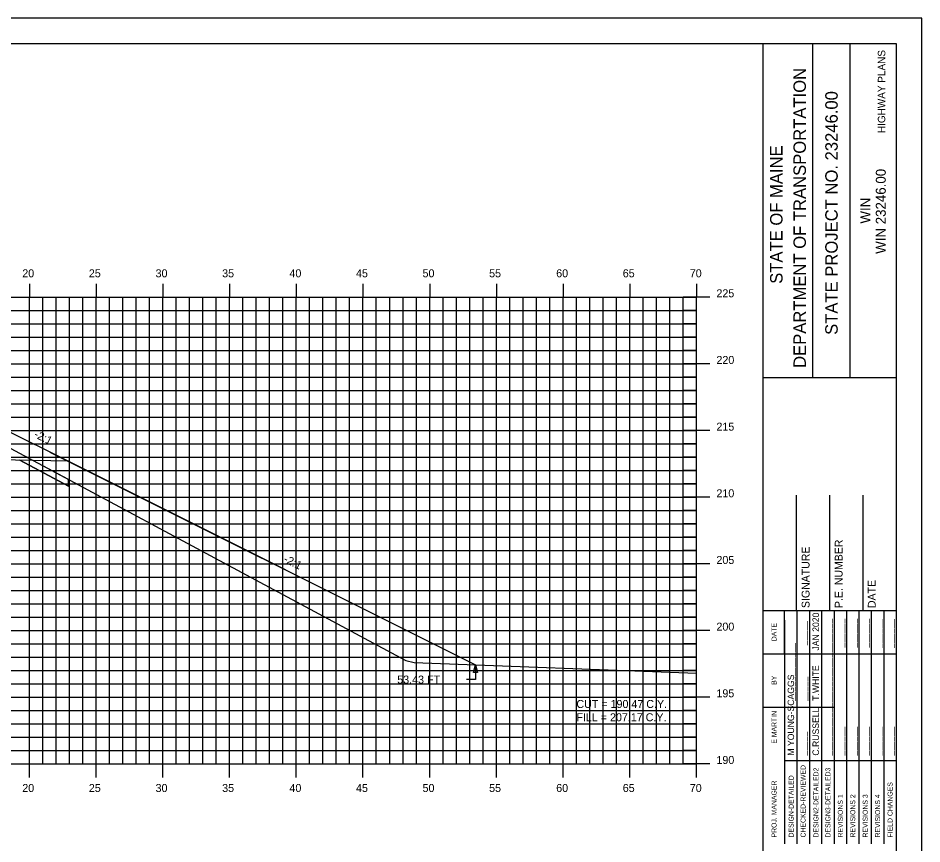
# Model space of a CAD drawing. Extents: x 1138320 to 1138490, y 608981 to 609091.
# Drawn here: x 1138421.8 to 1138489.6, y 609029.3 to 609091.3 of the extents above; entities that cross this region are included whole.
import ezdxf

# ---------------------------------------------------------------- set-up
doc = ezdxf.new("R2010")
doc.units = 0
for name, color, linetype in [('ANNOTATION', 7, 'Continuous'), ('BORDER', 7, 'Continuous'), ('D_Roadway_SlopeLines', 7, 'Continuous'), ('D_Roadway_SubGrade', 7, 'Continuous'), ('D_Text_Standard', 7, 'Continuous'), ('H_V ANNOTATION', 7, 'Continuous'), ('HIGHWAY_TITLE', 7, 'Continuous'), ('MAJOR', 7, 'Continuous'), ('MINOR', 7, 'Continuous'), ('PLOT BOUNDARY', 7, 'Continuous'), ('S_Roadway_Centerline', 7, 'Continuous'), ('SHADING', 7, 'Continuous')]:
    doc.layers.add(name, color=color, linetype=linetype)

msp = doc.modelspace()

# ---------------------------------------------------------------- linework, layer by layer
msp.add_lwpolyline([(1138347.192, 609041.753), (1138377.761, 609057.037), (1138379.761, 609058.037), (1138384.678, 609060.496), (1138384.679, 609060.496), (1138391.679, 609060.776), (1138402.679, 609060.996), (1138413.679, 609060.776), (1138420.679, 609060.496), (1138425.596, 609058.037), (1138427.596, 609057.037), (1138456.106, 609042.782)])
at = {"layer": 'BORDER'}
for p, q in [((1138477.679, 608984.335), (1138477.679, 609089.335)), ((1138481.408, 609064.332), (1138481.408, 609089.332)), ((1138484.203, 609064.332), (1138484.203, 609089.332)), ((1138477.68, 609064.329), (1138487.679, 609064.329)), ((1138480.179, 609046.838), (1138480.179, 609055.485)), ((1138482.679, 609046.838), (1138482.679, 609055.485)), ((1138485.179, 609046.838), (1138485.179, 609055.485)), ((1138477.679, 609046.838), (1138487.679, 609046.838))]:
    msp.add_line(p, q, dxfattribs=at)
msp.add_lwpolyline([(1138327.679, 608984.335), (1138487.679, 608984.335), (1138487.679, 609089.335), (1138327.679, 609089.335)], close=True, dxfattribs=at)
for points in [[(1138479.294, 609043.588), (1138479.294, 609046.838)], [(1138480.227, 609029.341), (1138480.227, 609046.838)], [(1138481.158, 609046.838), (1138481.158, 609029.341)], [(1138482.09, 609029.341), (1138482.09, 609046.838)], [(1138483.022, 609029.341), (1138483.022, 609046.838)], [(1138483.953, 609029.341), (1138483.953, 609046.838)], [(1138484.885, 609029.341), (1138484.885, 609046.838)], [(1138485.817, 609029.341), (1138485.817, 609046.838)], [(1138486.748, 609029.341), (1138486.748, 609046.838)], [(1138479.295, 609029.341), (1138479.295, 609046.132)], [(1138477.679, 609043.588), (1138487.679, 609043.588)], [(1138477.679, 609039.588), (1138479.295, 609039.588)], [(1138479.294, 609039.588), (1138483.021, 609039.588)], [(1138479.294, 609035.588), (1138487.679, 609035.588)]]:
    msp.add_lwpolyline(points, dxfattribs=at)
at = {"layer": 'D_Roadway_SlopeLines'}
for points in [[(1138424.207, 609058.732), (1138456.106, 609042.782)], [(1138425.596, 609056.659), (1138425.596, 609056.159), (1138421.957, 609058.11)], [(1138425.596, 609058.037), (1138427.596, 609057.037)], [(1138427.596, 609057.037), (1138456.106, 609042.782)]]:
    msp.add_lwpolyline(points, dxfattribs=at)
at = {"layer": 'D_Roadway_SubGrade'}
msp.add_lwpolyline([(1138413.679, 609060.359), (1138413.679, 609060.526), (1138420.679, 609060.246), (1138420.679, 609060.496), (1138420.679, 609060.496), (1138425.596, 609058.037), (1138413.679, 609058.276)], close=True, dxfattribs=at)
at = {"layer": 'D_Text_Standard'}
msp.add_lwpolyline([(1138456.106, 609042.782), (1138456.108, 609041.665), (1138455.428, 609041.665)], dxfattribs=at)
msp.add_lwpolyline([(1138456.106, 609042.782), (1138456.252, 609042.201), (1138455.961, 609042.2)], close=True, dxfattribs=at)
at = {"layer": 'MAJOR'}
for p, q in [((1138422.679, 609071.337), (1138422.679, 609070.335)), ((1138427.679, 609071.337), (1138427.679, 609070.335)), ((1138432.679, 609071.337), (1138432.679, 609070.335)), ((1138437.679, 609071.337), (1138437.679, 609070.335)), ((1138442.679, 609071.337), (1138442.679, 609070.335)), ((1138447.679, 609071.337), (1138447.679, 609070.335)), ((1138452.679, 609071.337), (1138452.679, 609070.335)), ((1138457.679, 609071.337), (1138457.679, 609070.335)), ((1138462.679, 609071.337), (1138462.679, 609070.335)), ((1138467.679, 609071.337), (1138467.679, 609070.335)), ((1138472.679, 609071.337), (1138472.679, 609070.335)), ((1138332.679, 609070.335), (1138472.679, 609070.335)), ((1138332.679, 609070.335), (1138472.679, 609070.335)), ((1138422.679, 609035.335), (1138422.679, 609070.335)), ((1138427.679, 609035.335), (1138427.679, 609070.335)), ((1138432.679, 609035.335), (1138432.679, 609070.335)), ((1138437.679, 609035.335), (1138437.679, 609070.335)), ((1138442.679, 609035.335), (1138442.679, 609070.335)), ((1138447.679, 609035.335), (1138447.679, 609070.335)), ((1138452.679, 609035.335), (1138452.679, 609070.335)), ((1138457.679, 609035.335), (1138457.679, 609070.335)), ((1138462.679, 609035.335), (1138462.679, 609070.335)), ((1138467.679, 609035.335), (1138467.679, 609070.335)), ((1138473.681, 609070.335), (1138471.677, 609070.335)), ((1138472.679, 609035.335), (1138472.679, 609070.335)), ((1138472.679, 609035.335), (1138472.679, 609070.335)), ((1138332.679, 609065.335), (1138472.679, 609065.335)), ((1138473.681, 609065.335), (1138471.677, 609065.335)), ((1138332.679, 609060.335), (1138472.679, 609060.335)), ((1138473.681, 609060.335), (1138471.677, 609060.335)), ((1138332.679, 609055.335), (1138472.679, 609055.335)), ((1138473.681, 609055.335), (1138471.677, 609055.335)), ((1138332.679, 609050.335), (1138472.679, 609050.335)), ((1138473.681, 609050.335), (1138471.677, 609050.335)), ((1138332.679, 609045.335), (1138472.679, 609045.335)), ((1138473.681, 609045.335), (1138471.677, 609045.335)), ((1138332.679, 609040.335), (1138472.679, 609040.335)), ((1138473.681, 609040.335), (1138471.677, 609040.335)), ((1138332.679, 609035.335), (1138472.679, 609035.335)), ((1138332.679, 609035.335), (1138472.679, 609035.335)), ((1138422.679, 609034.333), (1138422.679, 609035.335)), ((1138427.679, 609034.333), (1138427.679, 609035.335)), ((1138432.679, 609034.333), (1138432.679, 609035.335)), ((1138437.679, 609034.333), (1138437.679, 609035.335)), ((1138442.679, 609034.333), (1138442.679, 609035.335)), ((1138447.679, 609034.333), (1138447.679, 609035.335)), ((1138452.679, 609034.333), (1138452.679, 609035.335)), ((1138457.679, 609034.333), (1138457.679, 609035.335)), ((1138462.679, 609034.333), (1138462.679, 609035.335)), ((1138467.679, 609034.333), (1138467.679, 609035.335)), ((1138473.681, 609035.335), (1138471.677, 609035.335)), ((1138472.679, 609034.333), (1138472.679, 609035.335))]:
    msp.add_line(p, q, dxfattribs=at)
at = {"layer": 'MINOR'}
for p, q in [((1138423.679, 609035.335), (1138423.679, 609070.335)), ((1138424.679, 609035.335), (1138424.679, 609070.335)), ((1138425.679, 609035.335), (1138425.679, 609070.335)), ((1138426.679, 609035.335), (1138426.679, 609070.335)), ((1138428.679, 609035.335), (1138428.679, 609070.335)), ((1138429.679, 609035.335), (1138429.679, 609070.335)), ((1138430.679, 609035.335), (1138430.679, 609070.335)), ((1138431.679, 609035.335), (1138431.679, 609070.335)), ((1138433.679, 609035.335), (1138433.679, 609070.335)), ((1138434.679, 609035.335), (1138434.679, 609070.335)), ((1138435.679, 609035.335), (1138435.679, 609070.335)), ((1138436.679, 609035.335), (1138436.679, 609070.335)), ((1138438.679, 609035.335), (1138438.679, 609070.335)), ((1138439.679, 609035.335), (1138439.679, 609070.335)), ((1138440.679, 609035.335), (1138440.679, 609070.335)), ((1138441.679, 609035.335), (1138441.679, 609070.335)), ((1138443.679, 609035.335), (1138443.679, 609070.335)), ((1138444.679, 609035.335), (1138444.679, 609070.335)), ((1138445.679, 609035.335), (1138445.679, 609070.335)), ((1138446.679, 609035.335), (1138446.679, 609070.335)), ((1138448.679, 609035.335), (1138448.679, 609070.335)), ((1138449.679, 609035.335), (1138449.679, 609070.335)), ((1138450.679, 609035.335), (1138450.679, 609070.335)), ((1138451.679, 609035.335), (1138451.679, 609070.335)), ((1138453.679, 609035.335), (1138453.679, 609070.335)), ((1138454.679, 609035.335), (1138454.679, 609070.335)), ((1138455.679, 609035.335), (1138455.679, 609070.335)), ((1138456.679, 609035.335), (1138456.679, 609070.335)), ((1138458.679, 609035.335), (1138458.679, 609070.335)), ((1138459.679, 609035.335), (1138459.679, 609070.335)), ((1138460.679, 609035.335), (1138460.679, 609070.335)), ((1138461.679, 609035.335), (1138461.679, 609070.335)), ((1138463.679, 609035.335), (1138463.679, 609070.335)), ((1138464.679, 609035.335), (1138464.679, 609070.335)), ((1138465.679, 609035.335), (1138465.679, 609070.335)), ((1138466.679, 609035.335), (1138466.679, 609070.335)), ((1138468.679, 609035.335), (1138468.679, 609070.335)), ((1138469.679, 609035.335), (1138469.679, 609070.335)), ((1138470.679, 609035.335), (1138470.679, 609070.335)), ((1138471.679, 609035.335), (1138471.679, 609070.335)), ((1138332.679, 609069.335), (1138472.679, 609069.335)), ((1138472.679, 609069.335), (1138471.677, 609069.335)), ((1138332.679, 609068.335), (1138472.679, 609068.335)), ((1138472.679, 609068.335), (1138471.677, 609068.335)), ((1138332.679, 609067.335), (1138472.679, 609067.335)), ((1138472.679, 609067.335), (1138471.677, 609067.335)), ((1138332.679, 609066.335), (1138472.679, 609066.335)), ((1138472.679, 609066.335), (1138471.677, 609066.335)), ((1138332.679, 609064.335), (1138472.679, 609064.335)), ((1138472.679, 609064.335), (1138471.677, 609064.335)), ((1138332.679, 609063.335), (1138472.679, 609063.335)), ((1138472.679, 609063.335), (1138471.677, 609063.335)), ((1138332.679, 609062.335), (1138472.679, 609062.335)), ((1138472.679, 609062.335), (1138471.677, 609062.335)), ((1138332.679, 609061.335), (1138472.679, 609061.335)), ((1138472.679, 609061.335), (1138471.677, 609061.335)), ((1138332.679, 609059.335), (1138472.679, 609059.335)), ((1138472.679, 609059.335), (1138471.677, 609059.335)), ((1138332.679, 609058.335), (1138472.679, 609058.335)), ((1138472.679, 609058.335), (1138471.677, 609058.335)), ((1138332.679, 609057.335), (1138472.679, 609057.335)), ((1138472.679, 609057.335), (1138471.677, 609057.335)), ((1138332.679, 609056.335), (1138472.679, 609056.335)), ((1138472.679, 609056.335), (1138471.677, 609056.335)), ((1138332.679, 609054.335), (1138472.679, 609054.335)), ((1138472.679, 609054.335), (1138471.677, 609054.335)), ((1138332.679, 609053.335), (1138472.679, 609053.335)), ((1138472.679, 609053.335), (1138471.677, 609053.335)), ((1138332.679, 609052.335), (1138472.679, 609052.335)), ((1138472.679, 609052.335), (1138471.677, 609052.335)), ((1138332.679, 609051.335), (1138472.679, 609051.335)), ((1138472.679, 609051.335), (1138471.677, 609051.335)), ((1138332.679, 609049.335), (1138472.679, 609049.335)), ((1138472.679, 609049.335), (1138471.677, 609049.335)), ((1138332.679, 609048.335), (1138472.679, 609048.335)), ((1138472.679, 609048.335), (1138471.677, 609048.335)), ((1138332.679, 609047.335), (1138472.679, 609047.335)), ((1138472.679, 609047.335), (1138471.677, 609047.335)), ((1138332.679, 609046.335), (1138472.679, 609046.335)), ((1138472.679, 609046.335), (1138471.677, 609046.335)), ((1138332.679, 609044.335), (1138472.679, 609044.335)), ((1138472.679, 609044.335), (1138471.677, 609044.335)), ((1138332.679, 609043.335), (1138472.679, 609043.335)), ((1138472.679, 609043.335), (1138471.677, 609043.335)), ((1138332.679, 609042.335), (1138472.679, 609042.335)), ((1138472.679, 609042.335), (1138471.677, 609042.335)), ((1138332.679, 609041.335), (1138472.679, 609041.335)), ((1138472.679, 609041.335), (1138471.677, 609041.335)), ((1138332.679, 609039.335), (1138472.679, 609039.335)), ((1138472.679, 609039.335), (1138471.677, 609039.335)), ((1138332.679, 609038.335), (1138472.679, 609038.335)), ((1138472.679, 609038.335), (1138471.677, 609038.335)), ((1138332.679, 609037.335), (1138472.679, 609037.335)), ((1138472.679, 609037.335), (1138471.677, 609037.335)), ((1138332.679, 609036.335), (1138472.679, 609036.335)), ((1138472.679, 609036.335), (1138471.677, 609036.335))]:
    msp.add_line(p, q, dxfattribs=at)
at = {"layer": 'PLOT BOUNDARY'}
msp.add_lwpolyline([(1138319.586, 608981.276), (1138489.586, 608981.276), (1138489.586, 609091.276), (1138319.586, 609091.276)], close=True, dxfattribs=at)
at = {"layer": 'S_Roadway_Centerline'}
msp.add_lwpolyline([(1138332.679, 609041.616), (1138336.049, 609041.666), (1138348.96, 609041.767), (1138358.116, 609046.004), (1138359.488, 609046.419), (1138362.571, 609047.965), (1138383.071, 609058.302), (1138388, 609060.837), (1138390.649, 609061.402), (1138391.414, 609061.554), (1138391.787, 609061.616), (1138402.249, 609061.759), (1138402.804, 609061.769), (1138412.483, 609061.629), (1138413.106, 609061.62), (1138413.261, 609061.6), (1138416.451, 609061.498), (1138419.518, 609059.918), (1138450.838, 609043.119), (1138450.903, 609043.108), (1138451.517, 609042.958), (1138472.679, 609042.149)], dxfattribs=at)
at = {"layer": 'SHADING'}
for p, q in [((1138422.926, 609058.091), (1138421.957, 609058.11)), ((1138425.596, 609056.659), (1138422.926, 609058.091))]:
    msp.add_line(p, q, dxfattribs=at)
msp.add_lwpolyline([(1138421.957, 609058.11), (1138425.596, 609056.159), (1138425.596, 609056.659)], dxfattribs=at)

# ---------------------------------------------------------------- texts
at = {"layer": 'ANNOTATION'}
for rotation, p in [(333.4354, (1138422.961, 609059.873)), (333.43495, (1138441.674, 609050.516))]:
    msp.add_text('-2:1', height=0.6, rotation=rotation, dxfattribs=at).set_placement(p)
at = {"layer": 'BORDER'}
for s, height, p in [('DEPARTMENT OF TRANSPORTATION', 0.93176, (1138480.886, 609065.041)), ('STATE PROJECT NO. 23246.00', 0.93176, (1138483.271, 609067.517)), ('STATE OF MAINE', 0.93176, (1138479.135, 609071.347)), ('WIN 23246.00', 0.74527, (1138486.875, 609073.596)), ('WIN', 0.7453, (1138485.716, 609075.865)), ('P.E. NUMBER', 0.59055, (1138483.64, 609047.03)), ('SIGNATURE', 0.5906, (1138481.16, 609047.03)), ('DATE', 0.5906, (1138486.12, 609047.03)), ('JAN 2020', 0.4845, (1138481.866, 609043.843)), ('DATE', 0.3714, (1138478.684, 609044.544)), ('_____', 0.4845, (1138480.897, 609044.243)), ('______', 0.4845, (1138482.76, 609044.063)), ('______', 0.4845, (1138483.692, 609044.065)), ('______', 0.4845, (1138484.623, 609044.067)), ('______', 0.4845, (1138485.555, 609044.067)), ('______', 0.4845, (1138486.487, 609044.036)), ('______', 0.4845, (1138487.418, 609044.036)), ('____________', 0.48455, (1138480.002, 609040.073)), ('____________', 0.48455, (1138482.76, 609040.073)), ('T.WHITE', 0.4845, (1138481.866, 609040.073)), ('BY', 0.3714, (1138478.684, 609041.273)), ('M YOUNG-SCAGGS', 0.48455, (1138480.002, 609035.961)), ('_____', 0.4845, (1138480.934, 609040.073)), ('____________', 0.48455, (1138482.76, 609035.961)), ('E MARTIN', 0.3727, (1138478.684, 609036.855)), ('C.RUSSELL', 0.4845, (1138481.866, 609035.961)), ('_____', 0.4845, (1138480.897, 609035.961)), ('______', 0.4845, (1138483.692, 609035.961)), ('______', 0.4845, (1138484.623, 609035.961)), ('______', 0.4845, (1138485.555, 609035.961)), ('______', 0.4845, (1138486.487, 609035.961)), ('______', 0.4845, (1138487.418, 609035.961)), ('CHECKED-REVIEWED', 0.37275, (1138480.86, 609029.826)), ('DESIGN-DETAILED', 0.37275, (1138479.966, 609029.826)), ('DESIGN2-DETAILED2', 0.37275, (1138481.829, 609029.826)), ('DESIGN3-DETAILED3', 0.37275, (1138482.724, 609029.826)), ('PROJ. MANAGER', 0.37275, (1138478.684, 609029.826)), ('FIELD CHANGES', 0.37275, (1138487.382, 609029.826)), ('REVISIONS 1', 0.37275, (1138483.655, 609029.826)), ('REVISIONS 2', 0.37275, (1138484.587, 609029.826)), ('REVISIONS 3', 0.37275, (1138485.519, 609029.826)), ('REVISIONS 4', 0.37275, (1138486.45, 609029.826))]:
    msp.add_text(s, height=height, rotation=90, dxfattribs=at).set_placement(p)
at = {"layer": 'D_Text_Standard'}
for s, p in [('53.43 FT', (1138450.248, 609041.365)), ('CUT = 190.47 C.Y.', (1138463.679, 609039.535)), ('FILL = 207.17 C.Y.', (1138463.679, 609038.539))]:
    msp.add_text(s, height=0.6, dxfattribs=at).set_placement(p)
at = {"layer": 'H_V ANNOTATION'}
for s, p in [('20', (1138422.133, 609071.835)), ('25', (1138427.125, 609071.835)), ('30', (1138432.128, 609071.835)), ('35', (1138437.12, 609071.835)), ('40', (1138442.165, 609071.835)), ('45', (1138447.157, 609071.835)), ('50', (1138452.144, 609071.835)), ('55', (1138457.136, 609071.835)), ('60', (1138462.165, 609071.835)), ('65', (1138467.157, 609071.835)), ('70', (1138472.181, 609071.835)), ('225', (1138474.179, 609070.335)), ('220', (1138474.179, 609065.335)), ('215', (1138474.179, 609060.335)), ('210', (1138474.179, 609055.335)), ('205', (1138474.179, 609050.335)), ('200', (1138474.179, 609045.335)), ('195', (1138474.179, 609040.335)), ('190', (1138474.179, 609035.335)), ('20', (1138422.133, 609033.235)), ('25', (1138427.125, 609033.235)), ('30', (1138432.128, 609033.235)), ('35', (1138437.12, 609033.235)), ('40', (1138442.165, 609033.235)), ('45', (1138447.157, 609033.235)), ('50', (1138452.144, 609033.235)), ('55', (1138457.136, 609033.235)), ('60', (1138462.165, 609033.235)), ('65', (1138467.157, 609033.235)), ('70', (1138472.181, 609033.235))]:
    msp.add_text(s, height=0.6, dxfattribs=at).set_placement(p)
at = {"layer": 'HIGHWAY_TITLE'}
msp.add_text('HIGHWAY PLANS', height=0.55901, rotation=90, dxfattribs=at).set_placement((1138486.838, 609082.65))

doc.saveas('drawing.dxf')
